(* Logix 5000 project; controller SV160E2_EDS_AOI_Sample_RSLogix_V31 vendor 1 type 14 code 92 rev 31.11; software revision 31.00 *)

TASK MainTask (continuous, watchdog 500 ms) : MainProgram

MODULES
   Local : vendor 1 type 14 code 92 (ICP 0, rev 31.11)
      Ethernet : vendor 1 type 12 code 200 (ICP 2, Ethernet 192.168.0.5, rev 10.1)
         AMCI_SV160E2 : vendor 10 type 12 code 47 (Ethernet 192.168.0.50, rev 1.6, StandardDataDriven RPI 8 ms)
END_MODULES

ADD_ON_INSTRUCTION AMCI_SV160E2_Absolute_Move   (* revision 1.0, vendor AMCI, ExecuteEnableInFalse *)
// Revision note:
// 8/2019 Version 0 Initial release of SV160E2 Add On Instructions.
// 3/17/20 Version 1 replaced the generic EDS file with a more complete V1.6 EDS file.
VAR_INPUT
   Status_Word_0 : INT; {required}
        .11   // Set when there is an input error
        .12   // set when there is a command error
        .13   // set when there is a configuration error
        .0   // Set when the SV160E2 is moving CW
        .1   // Set when SV160E2 is moving CCW
        .7   // SV160E2 Move Complete bit
   Status_Word_1 : INT; {required}
        .15   // Set when SV160E2 is enabled
   Type_0_for_standard_1_for_indexed : BOOL;
   Target_Position : DINT; {required}
   Programmed_Speed : DINT; {required}
   Acceleration : INT; {required}
   Deceleration : INT; {required}
   Maximum_Move_Torque : INT;
END_VAR
VAR_IN_OUT
   AMCI_SV160E2_output_data : _000A:SV160E2_9125ACD4:O:0; {required}
END_VAR
VAR_OUTPUT
   EN : BOOL; {access Read Only, visible}   // AOI EN bit
   ER : BOOL; {access Read Only, visible}   // AOI ER bit
END_VAR
VAR
   command_data_block : INT[10];
        [0]   // Command Word 0
        [4]   // Upper Programmed Speed
        [2]   // Upper Target Position
        [1]   // Command Word 1
        [3]   // Lower Target Position
        [5]   // Lower Programmed Speed
END_VAR

ROUTINE EnableInFalse   (* ladder *)
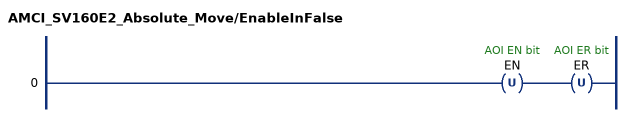
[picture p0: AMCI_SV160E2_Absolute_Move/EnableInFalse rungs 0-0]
   0: OTU(EN)OTU(ER);
END_ROUTINE

ROUTINE Logic   (* ladder *)
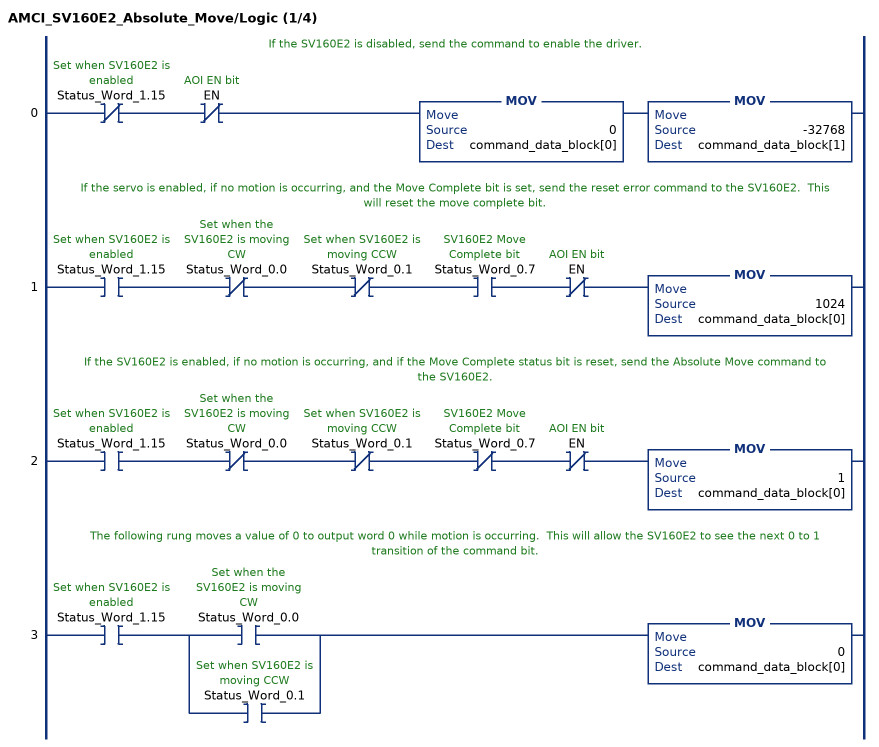
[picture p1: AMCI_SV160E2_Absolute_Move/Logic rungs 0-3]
   // If the SV160E2 is disabled, send the command to enable the driver.
   0: XIO(Status_Word_1.15)XIO(EN)MOV(0,command_data_block[0])MOV(-32768,command_data_block[1]);
   // If the servo is enabled, if no motion is occurring, and the Move Complete bit is set, send the reset error command to the SV160E2.  This will reset the move complete bit.
   1: XIC(Status_Word_1.15)XIO(Status_Word_0.0)XIO(Status_Word_0.1)XIC(Status_Word_0.7)XIO(EN)MOV(1024,command_data_block[0]);
   // If the SV160E2 is enabled, if no motion is occurring, and if the Move Complete status bit is reset, send the Absolute Move command to the SV160E2.
   2: XIC(Status_Word_1.15)XIO(Status_Word_0.0)XIO(Status_Word_0.1)XIO(Status_Word_0.7)XIO(EN)MOV(1,command_data_block[0]);
   // The following rung moves a value of 0 to output word 0 while motion is occurring.  This will allow the SV160E2 to see the next 0 to 1 transition of the command bit.
   3: XIC(Status_Word_1.15)[XIC(Status_Word_0.0) ,XIC(Status_Word_0.1) ]MOV(0,command_data_block[0]);
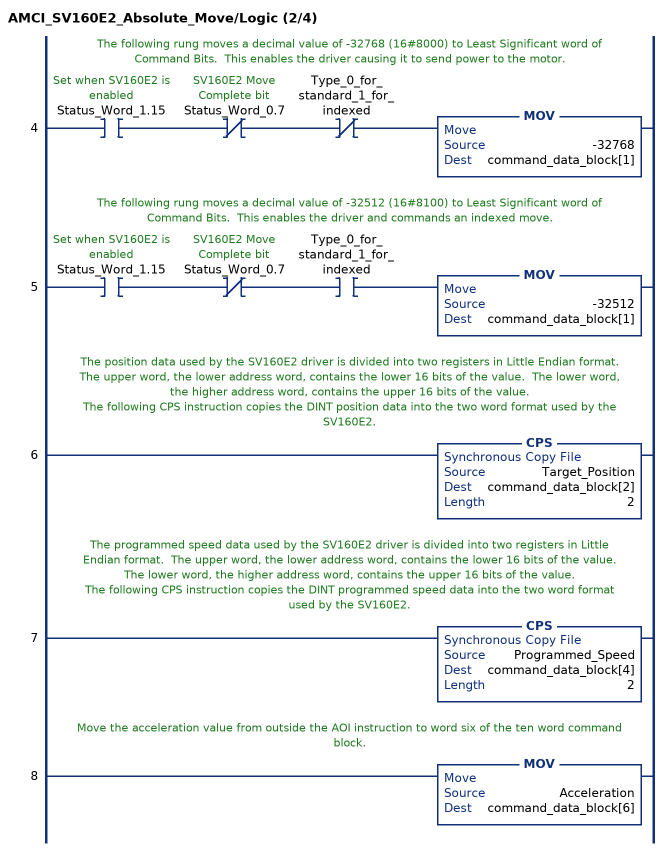
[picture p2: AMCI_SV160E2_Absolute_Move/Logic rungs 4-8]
   // The following rung moves a decimal value of -32768 (16#8000) to Least Significant word of Command Bits.  This enables the driver causing it to send power to the motor.
   4: XIC(Status_Word_1.15)XIO(Status_Word_0.7)XIO(Type_0_for_standard_1_for_indexed)MOV(-32768,command_data_block[1]);
   // The following rung moves a decimal value of -32512 (16#8100) to Least Significant word of Command Bits.  This enables the driver and commands an indexed move.
   5: XIC(Status_Word_1.15)XIO(Status_Word_0.7)XIC(Type_0_for_standard_1_for_indexed)MOV(-32512,command_data_block[1]);
   // The position data used by the SV160E2 driver is divided into two registers in Little Endian format.  The upper word, the lower address word, contains the lower 16 bits of the value.  The lower word, the higher address word, contains the upper 16 bits of the value.
   // The following CPS instruction copies the DINT position data into the two word format used by the SV160E2.
   6: CPS(Target_Position,command_data_block[2],2);
   // The programmed speed data used by the SV160E2 driver is divided into two registers in Little Endian format.  The upper word, the lower address word, contains the lower 16 bits of the value.  The lower word, the higher address word, contains the upper 16 bits of the value.
   // The following CPS instruction copies the DINT programmed speed data into the two word format used by the SV160E2.
   7: CPS(Programmed_Speed,command_data_block[4],2);
   // Move the acceleration value from outside the AOI instruction to word six of the ten word command block.
   8: MOV(Acceleration,command_data_block[6]);
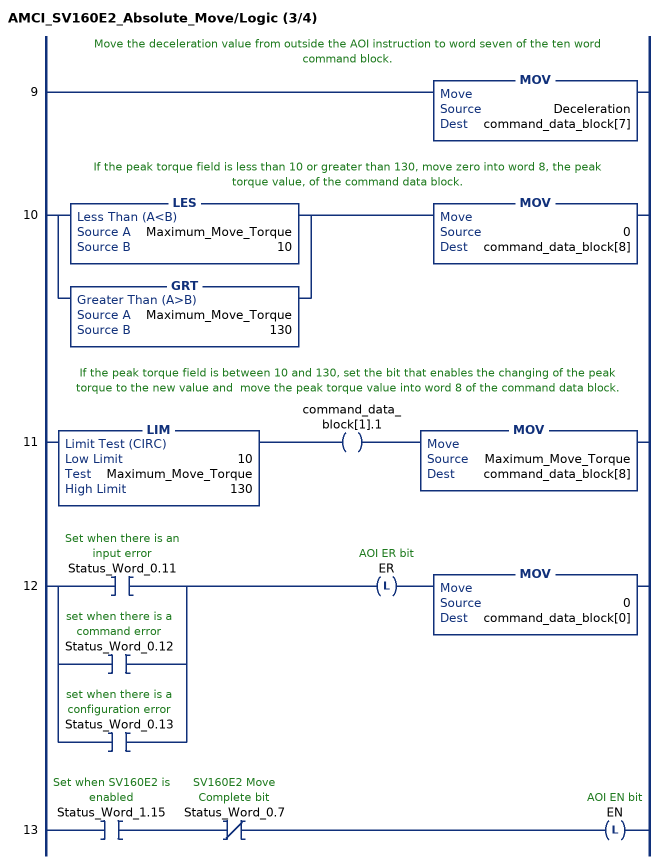
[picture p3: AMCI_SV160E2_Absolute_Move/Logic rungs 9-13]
   // Move the deceleration value from outside the AOI instruction to word seven of the ten word command block.
   9: MOV(Deceleration,command_data_block[7]);
   // If the peak torque field is less than 10 or greater than 130, move zero into word 8, the peak torque value, of the command data block.
   10: [LES(Maximum_Move_Torque,10) ,GRT(Maximum_Move_Torque,130) ]MOV(0,command_data_block[8]);
   // If the peak torque field is between 10 and 130, set the bit that enables the changing of the peak torque to the new value and  move the peak torque value into word 8 of the command data block.
   11: LIM(10,Maximum_Move_Torque,130)OTE(command_data_block[1].1)MOV(Maximum_Move_Torque,command_data_block[8]);
   12: [XIC(Status_Word_0.11) ,XIC(Status_Word_0.12) ,XIC(Status_Word_0.13) ]OTL(ER)MOV(0,command_data_block[0]);
   13: XIC(Status_Word_1.15)XIO(Status_Word_0.7)OTL(EN);
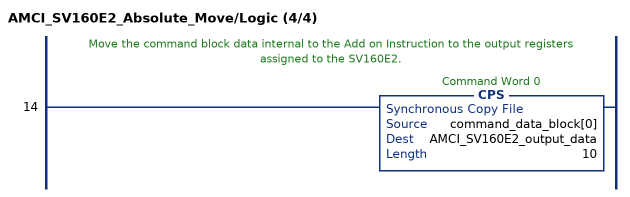
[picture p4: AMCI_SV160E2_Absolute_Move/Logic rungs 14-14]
   // Move the command block data internal to the Add on Instruction to the output registers assigned to the SV160E2.
   14: CPS(command_data_block[0],AMCI_SV160E2_output_data,10);
END_ROUTINE
END_ADD_ON_INSTRUCTION

ADD_ON_INSTRUCTION AMCI_SV160E2_Axis_Follower_Circular   (* revision 1.0, vendor AMCI, ExecuteEnableInFalse *)
// Revision note:
// 8/2019 Version 0 Initial release of SV160E2 Add On Instructions.
// 3/17/20 Version 13/17/20 Version 1 replaced the generic EDS file with a more complete V1.6 EDS file.  Also added a line of code to limit the minimum follower acceleration to -15999.
// Help:
// 2/2017: V0 is the initial release
// 7/2017: V1 added enable and error bits.
// 5/2019: V2 added unlatching the error bit when the rung goes false and the ability to select between normal (jog CCW) and continuous follower (jog CW)
VAR_OUTPUT
   EN : BOOL; {visible}
END_VAR
VAR_INPUT
   Status_Word_0 : INT; {required}
        .0   // set when moving CW
        .1   // set when moving CCW
        .3   // set when stopped
   Status_Word_1 : INT; {required}
        .15   // 0 when disabled 1 when enabled
   Follower_Position : REAL; {required}
   Follower_Velocity : REAL; {required}
   Follower_Acceleration : REAL; {required}
   Ramp_Acceleration : INT; {required}
   Deceleration : INT; {required}
   Conversion_Constant : REAL; {required}
   Position_Unwind : DINT; {required}
   Maximum_Move_Torque : INT;
END_VAR
VAR_IN_OUT
   AMCI_SV160E2_output_data : _000A:SV160E2_9125ACD4:O:0; {required}
END_VAR
VAR_OUTPUT
   Axis_Follower_occurring : BOOL; {visible}
   ER : BOOL; {visible}
END_VAR
VAR
   command_data_block : INT[10];
        [1]   // Command Bits LSW
        [0]   // Command Bits MSW
        [5]   // Lower Programmed Speed
        [2]   // Upper Target Position
        [4]   // Upper Programmed Speed
        [8]   // Unwind value when stopped, Maximum Move Torque when motion occurring
        [3]   // Lower Target Position
   axis_follower_position : DINT;
   axis_follower_velocity : DINT;
   axis_follower_acceleration : DINT; {access None}
END_VAR

ROUTINE EnableInFalse   (* ladder *)
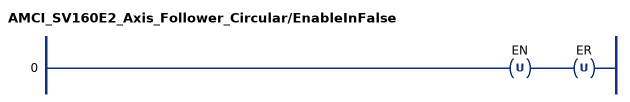
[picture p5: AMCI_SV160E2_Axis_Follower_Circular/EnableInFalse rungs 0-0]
   0: OTU(EN)OTU(ER);
END_ROUTINE

ROUTINE Logic   (* ladder *)
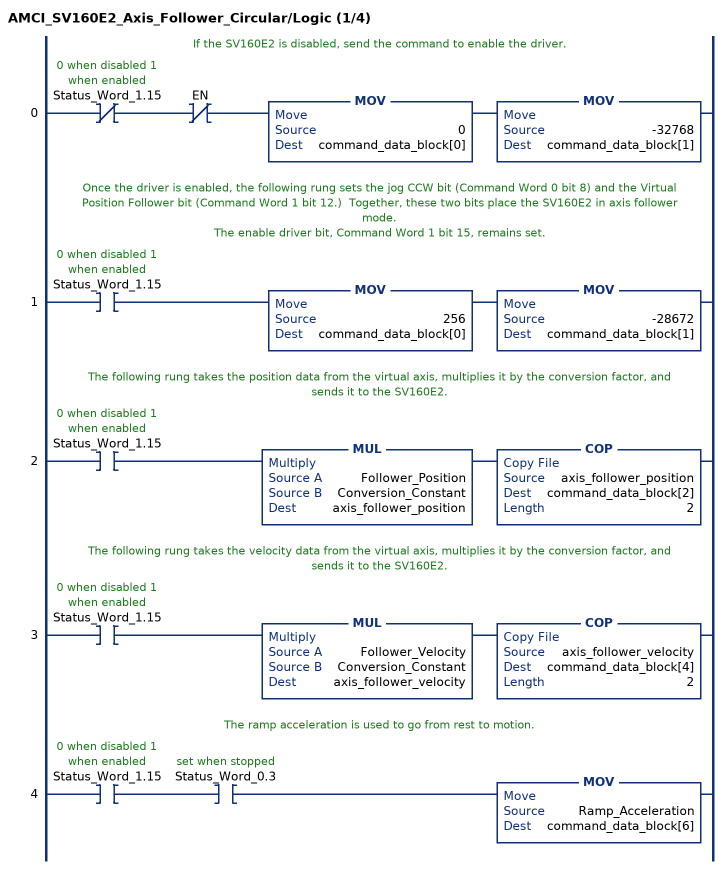
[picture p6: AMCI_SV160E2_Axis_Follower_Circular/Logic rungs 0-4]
   // If the SV160E2 is disabled, send the command to enable the driver.
   0: XIO(Status_Word_1.15)XIO(EN)MOV(0,command_data_block[0])MOV(-32768,command_data_block[1]);
   // Once the driver is enabled, the following rung sets the jog CCW bit (Command Word 0 bit 8) and the Virtual Position Follower bit (Command Word 1 bit 12.)  Together, these two bits place the SV160E2 in axis follower mode.
   // The enable driver bit, Command Word 1 bit 15, remains set.
   1: XIC(Status_Word_1.15)MOV(256,command_data_block[0])MOV(-28672,command_data_block[1]);
   // The following rung takes the position data from the virtual axis, multiplies it by the conversion factor, and sends it to the SV160E2.
   2: XIC(Status_Word_1.15)MUL(Follower_Position,Conversion_Constant,axis_follower_position)COP(axis_follower_position,command_data_block[2],2);
   // The following rung takes the velocity data from the virtual axis, multiplies it by the conversion factor, and sends it to the SV160E2.
   3: XIC(Status_Word_1.15)MUL(Follower_Velocity,Conversion_Constant,axis_follower_velocity)COP(axis_follower_velocity,command_data_block[4],2);
   // The ramp acceleration is used to go from rest to motion.
   4: XIC(Status_Word_1.15)XIC(Status_Word_0.3)MOV(Ramp_Acceleration,command_data_block[6]);
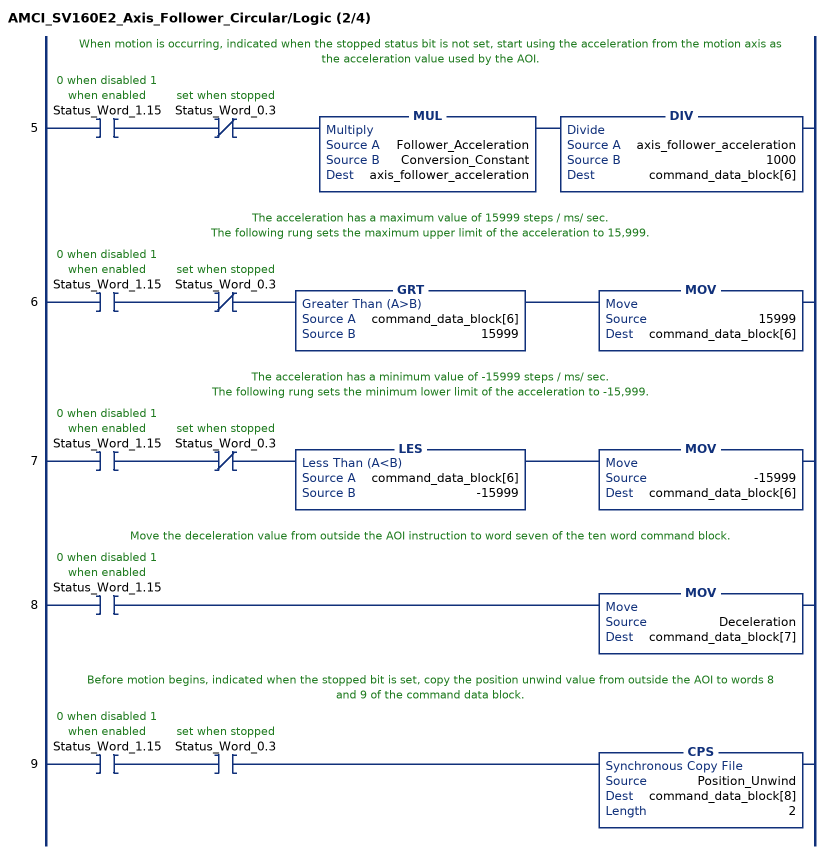
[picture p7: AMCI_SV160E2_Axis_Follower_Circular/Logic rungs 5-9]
   // When motion is occurring, indicated when the stopped status bit is not set, start using the acceleration from the motion axis as the acceleration value used by the AOI.
   5: XIC(Status_Word_1.15)XIO(Status_Word_0.3)MUL(Follower_Acceleration,Conversion_Constant,axis_follower_acceleration)DIV(axis_follower_acceleration,1000,command_data_block[6]);
   // The acceleration has a maximum value of 15999 steps / ms/ sec.
   // The following rung sets the maximum upper limit of the acceleration to 15,999.
   6: XIC(Status_Word_1.15)XIO(Status_Word_0.3)GRT(command_data_block[6],15999)MOV(15999,command_data_block[6]);
   // The acceleration has a minimum value of -15999 steps / ms/ sec.
   // The following rung sets the minimum lower limit of the acceleration to -15,999.
   7: XIC(Status_Word_1.15)XIO(Status_Word_0.3)LES(command_data_block[6],-15999)MOV(-15999,command_data_block[6]);
   // Move the deceleration value from outside the AOI instruction to word seven of the ten word command block.
   8: XIC(Status_Word_1.15)MOV(Deceleration,command_data_block[7]);
   // Before motion begins, indicated when the stopped bit is set, copy the position unwind value from outside the AOI to words 8 and 9 of the command data block.
   9: XIC(Status_Word_1.15)XIC(Status_Word_0.3)CPS(Position_Unwind,command_data_block[8],2);
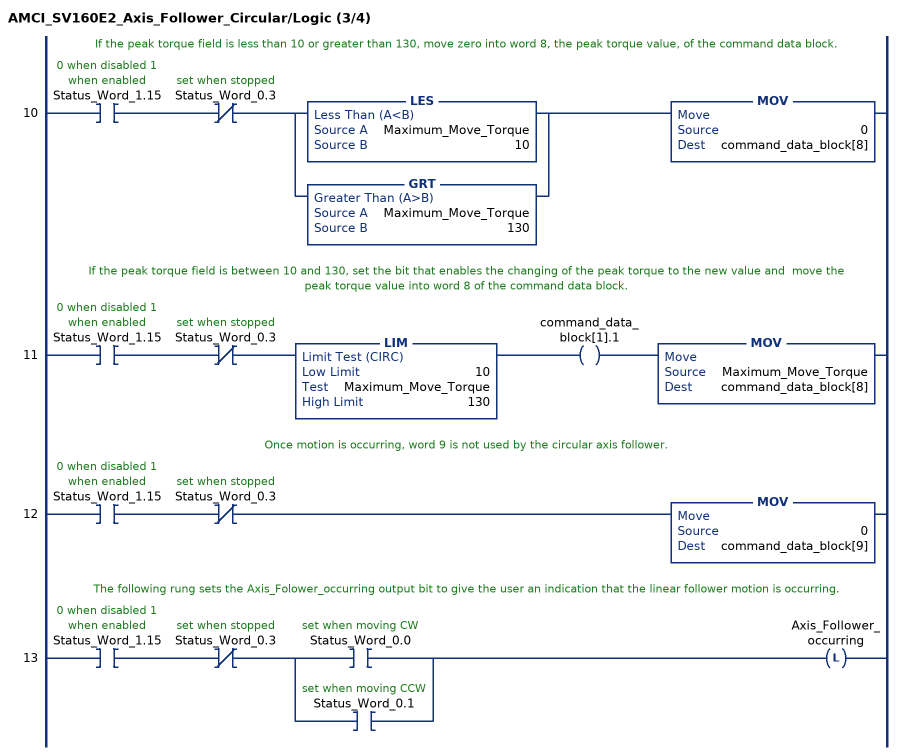
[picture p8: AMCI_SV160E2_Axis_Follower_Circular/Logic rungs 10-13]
   // If the peak torque field is less than 10 or greater than 130, move zero into word 8, the peak torque value, of the command data block.
   10: XIC(Status_Word_1.15)XIO(Status_Word_0.3)[LES(Maximum_Move_Torque,10) ,GRT(Maximum_Move_Torque,130) ]MOV(0,command_data_block[8]);
   // If the peak torque field is between 10 and 130, set the bit that enables the changing of the peak torque to the new value and  move the peak torque value into word 8 of the command data block.
   11: XIC(Status_Word_1.15)XIO(Status_Word_0.3)LIM(10,Maximum_Move_Torque,130)OTE(command_data_block[1].1)MOV(Maximum_Move_Torque,command_data_block[8]);
   // Once motion is occurring, word 9 is not used by the circular axis follower.
   12: XIC(Status_Word_1.15)XIO(Status_Word_0.3)MOV(0,command_data_block[9]);
   // The following rung sets the Axis_Folower_occurring output bit to give the user an indication that the linear follower motion is occurring.
   13: XIC(Status_Word_1.15)XIO(Status_Word_0.3)[XIC(Status_Word_0.0) ,XIC(Status_Word_0.1) ]OTL(Axis_Follower_occurring);
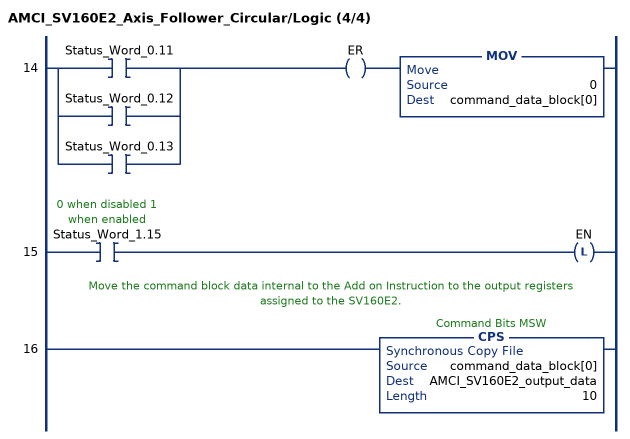
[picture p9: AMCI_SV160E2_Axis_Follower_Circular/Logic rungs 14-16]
   14: [XIC(Status_Word_0.11) ,XIC(Status_Word_0.12) ,XIC(Status_Word_0.13) ]OTE(ER)MOV(0,command_data_block[0]);
   15: XIC(Status_Word_1.15)OTL(EN);
   // Move the command block data internal to the Add on Instruction to the output registers assigned to the SV160E2.
   16: CPS(command_data_block[0],AMCI_SV160E2_output_data,10);
END_ROUTINE
END_ADD_ON_INSTRUCTION

ADD_ON_INSTRUCTION AMCI_SV160E2_Axis_Follower_Linear   (* revision 1.0, vendor AMCI, ExecuteEnableInFalse *)
// Revision note:
// 8/2019 Version 0 Initial release of SV160E2 Add On Instructions.
// 3/72020 Version 1 3/17/20 Version 1 replaced the generic EDS file with a more complete V1.6 EDS file.  Also added a line of code to limit the minimum follower acceleration to -15999.
// Help:
// 2/2017: V0 is the initial release
// 7/2017: V1 added enable and error bits.
// 5/2019: V2 added unlatching the error bit when the rung goes false and the ability to select between normal (jog CCW) and continuous follower (jog CW)
VAR_OUTPUT
   EN : BOOL; {visible}
END_VAR
VAR_INPUT
   Status_Word_0 : INT; {required}
        .0   // set when moving CW
        .1   // set when moving CCW
        .3   // set when stopped
   Status_Word_1 : INT; {required}
        .15   // 0 when disabled 1 when enabled
   Follower_Position : REAL; {required}
   Follower_Velocity : REAL; {required}
   Follower_Acceleration : REAL; {required}
   Ramp_Acceleration : INT; {required}
   Deceleration : INT; {required}
   Maximum_Move_Torque : INT;
END_VAR
VAR_IN_OUT
   AMCI_SV160E2_output_data : _000A:SV160E2_9125ACD4:O:0; {required}
END_VAR
VAR_OUTPUT
   Axis_Follower_occurring : BOOL; {visible}
   ER : BOOL; {visible}
END_VAR
VAR
   command_data_block : INT[10];
        [2]   // Upper Target Position
        [1]   // Command Bits LSW
        [3]   // Lower Target Position
        [5]   // Lower Programmed Speed
        [0]   // Command Bits MSW
        [4]   // Upper Programmed Speed
   axis_follower_position : DINT;
   axis_follower_velocity : DINT;
END_VAR

ROUTINE EnableInFalse   (* ladder *)
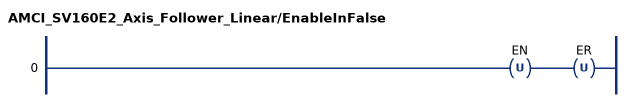
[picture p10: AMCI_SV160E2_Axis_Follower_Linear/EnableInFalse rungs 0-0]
   0: OTU(EN)OTU(ER);
END_ROUTINE

ROUTINE Logic   (* ladder *)
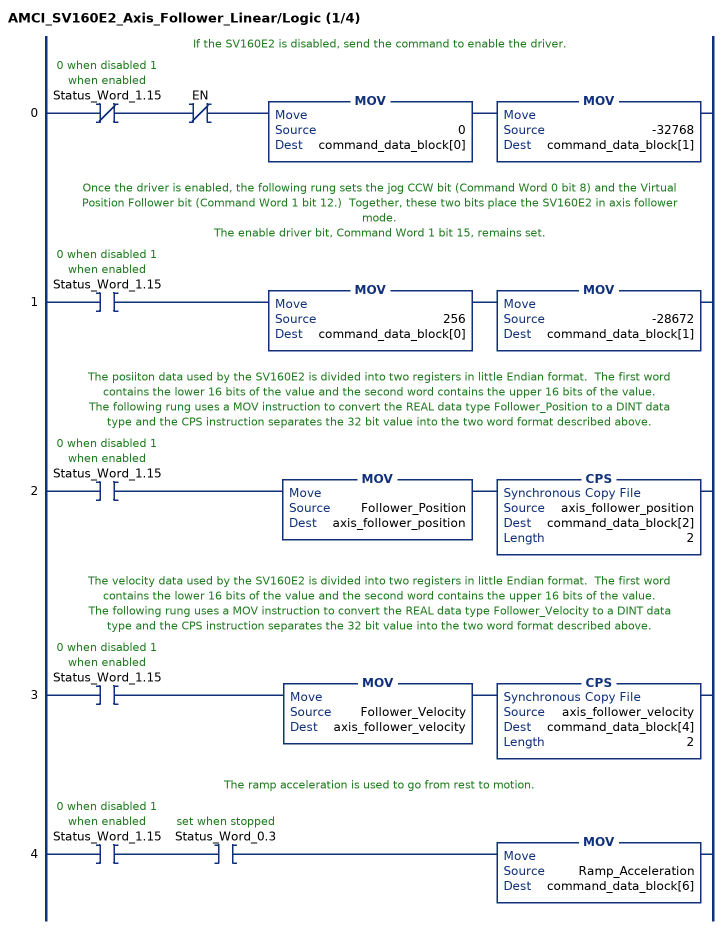
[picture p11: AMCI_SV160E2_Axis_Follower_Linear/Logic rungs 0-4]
   // If the SV160E2 is disabled, send the command to enable the driver.
   0: XIO(Status_Word_1.15)XIO(EN)MOV(0,command_data_block[0])MOV(-32768,command_data_block[1]);
   // Once the driver is enabled, the following rung sets the jog CCW bit (Command Word 0 bit 8) and the Virtual Position Follower bit (Command Word 1 bit 12.)  Together, these two bits place the SV160E2 in axis follower mode.
   // The enable driver bit, Command Word 1 bit 15, remains set.
   1: XIC(Status_Word_1.15)MOV(256,command_data_block[0])MOV(-28672,command_data_block[1]);
   // The posiiton data used by the SV160E2 is divided into two registers in little Endian format.  The first word contains the lower 16 bits of the value and the second word contains the upper 16 bits of the value.
   // The following rung uses a MOV instruction to convert the REAL data type Follower_Position to a DINT data type and the CPS instruction separates the 32 bit value into the two word format described above.
   2: XIC(Status_Word_1.15)MOV(Follower_Position,axis_follower_position)CPS(axis_follower_position,command_data_block[2],2);
   // The velocity data used by the SV160E2 is divided into two registers in little Endian format.  The first word contains the lower 16 bits of the value and the second word contains the upper 16 bits of the value.
   // The following rung uses a MOV instruction to convert the REAL data type Follower_Velocity to a DINT data type and the CPS instruction separates the 32 bit value into the two word format described above.
   3: XIC(Status_Word_1.15)MOV(Follower_Velocity,axis_follower_velocity)CPS(axis_follower_velocity,command_data_block[4],2);
   // The ramp acceleration is used to go from rest to motion.
   4: XIC(Status_Word_1.15)XIC(Status_Word_0.3)MOV(Ramp_Acceleration,command_data_block[6]);
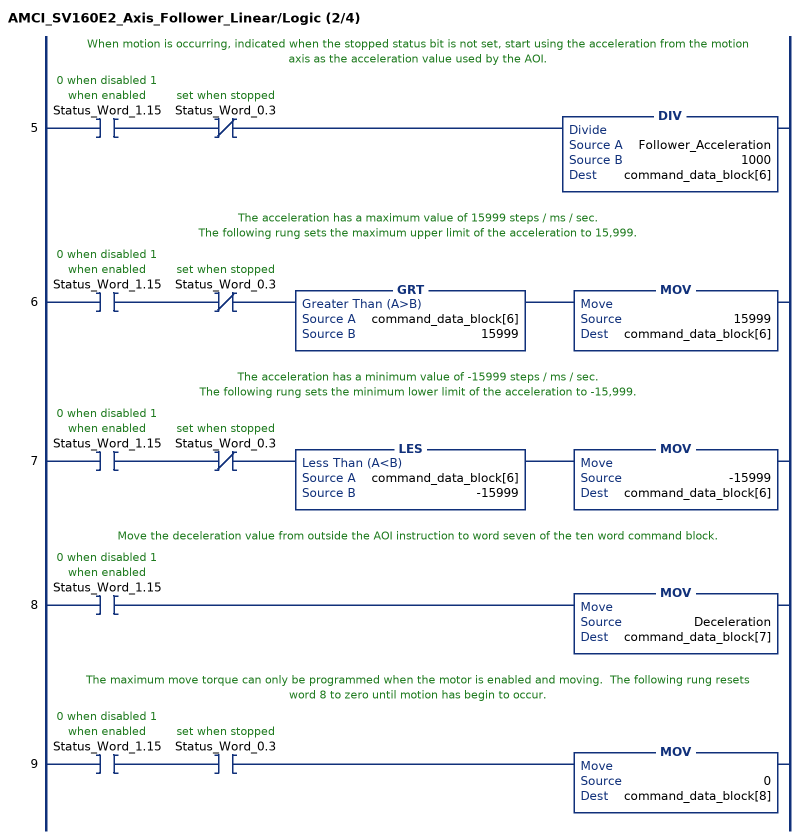
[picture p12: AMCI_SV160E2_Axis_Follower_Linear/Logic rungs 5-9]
   // When motion is occurring, indicated when the stopped status bit is not set, start using the acceleration from the motion axis as the acceleration value used by the AOI.
   5: XIC(Status_Word_1.15)XIO(Status_Word_0.3)DIV(Follower_Acceleration,1000,command_data_block[6]);
   // The acceleration has a maximum value of 15999 steps / ms / sec.
   // The following rung sets the maximum upper limit of the acceleration to 15,999.
   6: XIC(Status_Word_1.15)XIO(Status_Word_0.3)GRT(command_data_block[6],15999)MOV(15999,command_data_block[6]);
   // The acceleration has a minimum value of -15999 steps / ms / sec.
   // The following rung sets the minimum lower limit of the acceleration to -15,999.
   7: XIC(Status_Word_1.15)XIO(Status_Word_0.3)LES(command_data_block[6],-15999)MOV(-15999,command_data_block[6]);
   // Move the deceleration value from outside the AOI instruction to word seven of the ten word command block.
   8: XIC(Status_Word_1.15)MOV(Deceleration,command_data_block[7]);
   // The maximum move torque can only be programmed when the motor is enabled and moving.  The following rung resets word 8 to zero until motion has begin to occur.
   9: XIC(Status_Word_1.15)XIC(Status_Word_0.3)MOV(0,command_data_block[8]);
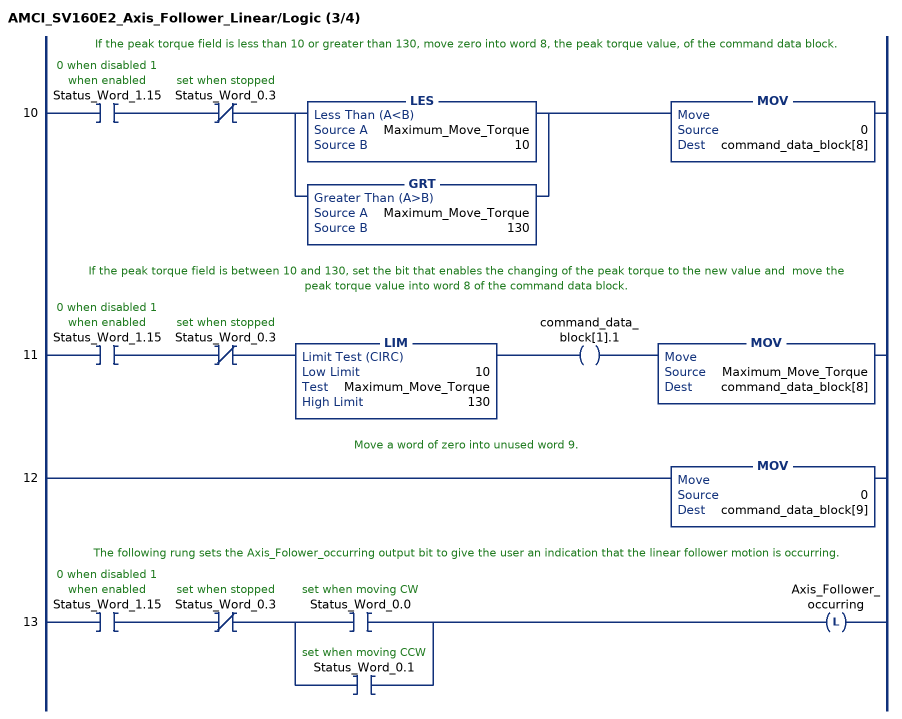
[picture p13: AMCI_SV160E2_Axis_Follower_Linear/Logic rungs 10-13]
   // If the peak torque field is less than 10 or greater than 130, move zero into word 8, the peak torque value, of the command data block.
   10: XIC(Status_Word_1.15)XIO(Status_Word_0.3)[LES(Maximum_Move_Torque,10) ,GRT(Maximum_Move_Torque,130) ]MOV(0,command_data_block[8]);
   // If the peak torque field is between 10 and 130, set the bit that enables the changing of the peak torque to the new value and  move the peak torque value into word 8 of the command data block.
   11: XIC(Status_Word_1.15)XIO(Status_Word_0.3)LIM(10,Maximum_Move_Torque,130)OTE(command_data_block[1].1)MOV(Maximum_Move_Torque,command_data_block[8]);
   // Move a word of zero into unused word 9.
   12: MOV(0,command_data_block[9]);
   // The following rung sets the Axis_Folower_occurring output bit to give the user an indication that the linear follower motion is occurring.
   13: XIC(Status_Word_1.15)XIO(Status_Word_0.3)[XIC(Status_Word_0.0) ,XIC(Status_Word_0.1) ]OTL(Axis_Follower_occurring);
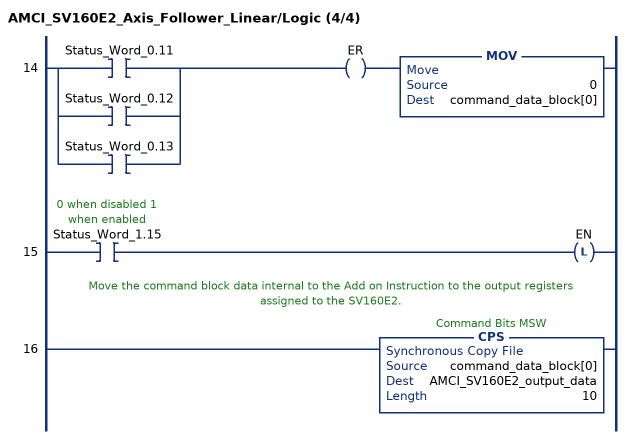
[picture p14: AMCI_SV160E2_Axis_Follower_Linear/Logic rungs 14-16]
   14: [XIC(Status_Word_0.11) ,XIC(Status_Word_0.12) ,XIC(Status_Word_0.13) ]OTE(ER)MOV(0,command_data_block[0]);
   15: XIC(Status_Word_1.15)OTL(EN);
   // Move the command block data internal to the Add on Instruction to the output registers assigned to the SV160E2.
   16: CPS(command_data_block[0],AMCI_SV160E2_output_data,10);
END_ROUTINE
END_ADD_ON_INSTRUCTION

ADD_ON_INSTRUCTION AMCI_SV160E2_Disable   (* revision 1.0, vendor AMCI *)
// Revision note:
// 8/2019 Version 0 Initial release of SV160E2 Add On Instructions.
// 3/17/20 Version 1 replaced the generic EDS file with a more complete V1.6 EDS file.
VAR_IN_OUT
   AMCI_SV160E2_OUTPUT_DATA : _000A:SV160E2_9125ACD4:O:0; {required}
END_VAR
VAR
   command_data_block : INT[10];
        [1]   // Command Bits LSW
        [3]   // Lower Target Position
        [5]   // Lower Programmed Speed
        [0]   // Command Bits MSW
        [2]   // Upper Target Position
        [4]   // Upper Programmed Speed
END_VAR

ROUTINE Logic   (* ladder *)
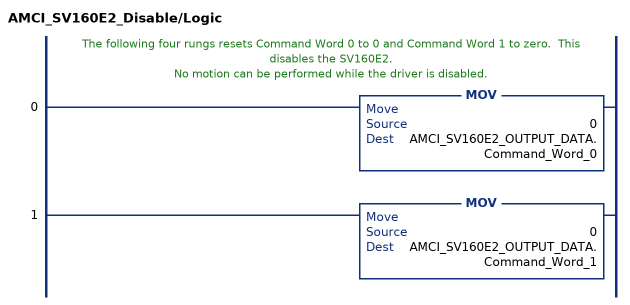
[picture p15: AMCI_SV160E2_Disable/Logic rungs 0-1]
   // The following four rungs resets Command Word 0 to 0 and Command Word 1 to zero.  This disables the SV160E2.
   // No motion can be performed while the driver is disabled.
   0: MOV(0,AMCI_SV160E2_OUTPUT_DATA.Command_Word_0);
   1: MOV(0,AMCI_SV160E2_OUTPUT_DATA.Command_Word_1);
END_ROUTINE
END_ADD_ON_INSTRUCTION

ADD_ON_INSTRUCTION AMCI_SV160E2_Enable   (* revision 1.0, vendor AMCI *)
// Revision note:
// 8/2019 Version 0 Initial release of SV160E2 Add On Instructions.
// 3/17/20 Version 1 replaced the generic EDS file with a more complete V1.6 EDS file.
VAR_IN_OUT
   AMCI_SV160E2_OUTPUT_DATA : _000A:SV160E2_9125ACD4:O:0; {required}
END_VAR
VAR
   command_data_block : INT[10];
        [1]   // Command Bits LSW
        [3]   // Lower Target Position
        [5]   // Lower Programmed Speed
        [0]   // Command Bits MSW
        [2]   // Upper Target Position
        [4]   // Upper Programmed Speed
END_VAR

ROUTINE Logic   (* ladder *)
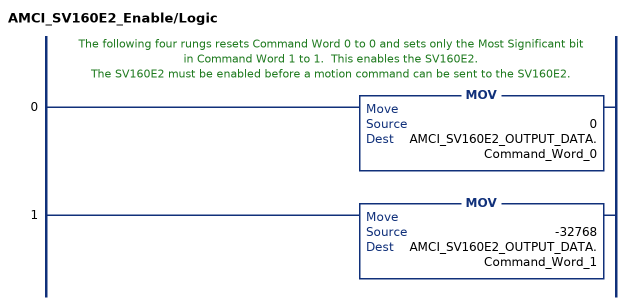
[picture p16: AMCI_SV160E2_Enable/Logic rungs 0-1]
   // The following four rungs resets Command Word 0 to 0 and sets only the Most Significant bit in Command Word 1 to 1.  This enables the SV160E2.
   // The SV160E2 must be enabled before a motion command can be sent to the SV160E2.
   0: MOV(0,AMCI_SV160E2_OUTPUT_DATA.Command_Word_0);
   1: MOV(-32768,AMCI_SV160E2_OUTPUT_DATA.Command_Word_1);
END_ROUTINE
END_ADD_ON_INSTRUCTION

ADD_ON_INSTRUCTION AMCI_SV160E2_Hold   (* revision 1.0, vendor AMCI *)
// Revision note:
// 8/2019 Version 0 Initial release of SV160E2 Add On Instructions.
// 3/17/20 Version 1 replaced the generic EDS file with a more complete V1.6 EDS file.
VAR_IN_OUT
   AMCI_SV160E2_OUTPUT_DATA : _000A:SV160E2_9125ACD4:O:0; {required}
END_VAR
VAR
   command_data_block : INT[10];
        [1]   // Command Bits LSW
        [3]   // Lower Target Position
        [5]   // Lower Programmed Speed
        [0]   // Command Bits MSW
        [2]   // Upper Target Position
        [4]   // Upper Programmed Speed
END_VAR

ROUTINE Logic   (* ladder *)
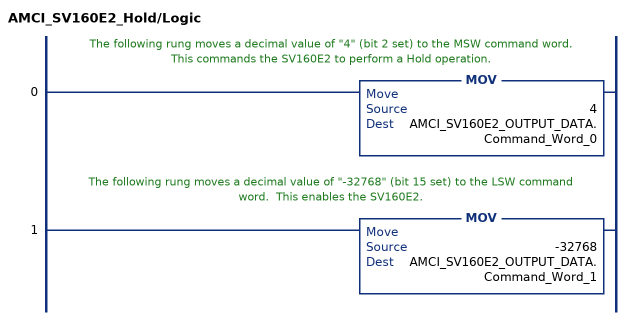
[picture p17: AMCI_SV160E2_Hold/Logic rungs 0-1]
   // The following rung moves a decimal value of "4" (bit 2 set) to the MSW command word.  This commands the SV160E2 to perform a Hold operation.
   0: MOV(4,AMCI_SV160E2_OUTPUT_DATA.Command_Word_0);
   // The following rung moves a decimal value of "-32768" (bit 15 set) to the LSW command word.  This enables the SV160E2.
   1: MOV(-32768,AMCI_SV160E2_OUTPUT_DATA.Command_Word_1);
END_ROUTINE
END_ADD_ON_INSTRUCTION
